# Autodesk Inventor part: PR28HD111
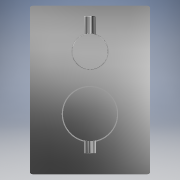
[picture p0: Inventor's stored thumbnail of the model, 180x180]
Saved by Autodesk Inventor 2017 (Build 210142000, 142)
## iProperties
Created: 2021-04
Part Number: PR28HD111
Material: Generico
Document SubType Name: Modeling
Designer: PIZZERA
Density: 1 g/cm^3
Appearance: Default
Author: PIZZERA
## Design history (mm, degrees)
feature "Base4"
node "Solido1"
node "Solido5"
